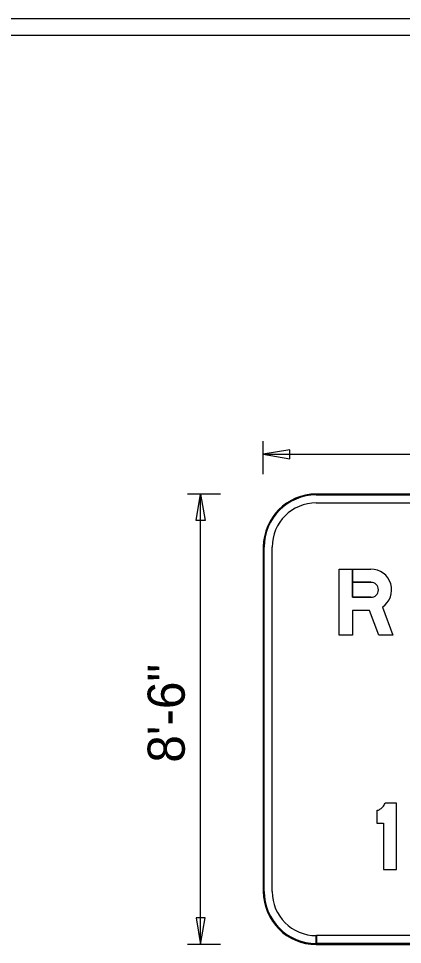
# Model space of a CAD drawing. Extents: x 10268147 to 10268469, y 2141099 to 2141204.
# Drawn here: x 10268191.41 to 10268198.66, y 2141186.48 to 2141203.96 of the extents above; entities that cross this region are included whole.
import ezdxf

# ---------------------------------------------------------------- set-up
doc = ezdxf.new("R2010")
doc.units = 0
for name, color, linetype in [('61', 7, 'Continuous'), ('GSDims', 7, 'Continuous'), ('PlotBorder_dp', 7, 'Continuous'), ('SheetLinesMisc2_dp', 7, 'Continuous')]:
    doc.layers.add(name, color=color, linetype=linetype)

msp = doc.modelspace()

# ---------------------------------------------------------------- linework, layer by layer
at = {"layer": '61'}
msp.add_line((10268153.875, 2141203.638), (10268229.209, 2141203.638), dxfattribs=at)
at = {"layer": 'GSDims'}
for p, q in [((10268196.031, 2141195.358), (10268196.031, 2141195.983)), ((10268196.031, 2141195.733), (10268211.031, 2141195.733)), ((10268195.224, 2141194.983), (10268194.599, 2141194.983)), ((10268194.849, 2141186.483), (10268194.849, 2141194.983)), ((10268195.224, 2141186.483), (10268194.599, 2141186.483))]:
    msp.add_line(p, q, dxfattribs=at)
for points in [[(10268196.031, 2141195.733), (10268196.531, 2141195.65), (10268196.531, 2141195.817)], [(10268194.849, 2141194.983), (10268194.932, 2141194.483), (10268194.766, 2141194.483)], [(10268194.849, 2141186.483), (10268194.932, 2141186.983), (10268194.766, 2141186.983)]]:
    msp.add_lwpolyline(points, close=True, dxfattribs=at)
at = {"layer": 'PlotBorder_dp'}
for p, q in [((10268210.031, 2141194.983), (10268197.031, 2141194.983)), ((10268210.031, 2141194.983), (10268197.031, 2141194.983)), ((10268210.031, 2141194.983), (10268197.031, 2141194.983)), ((10268210.031, 2141194.983), (10268197.031, 2141194.983)), ((10268197.031, 2141194.967), (10268210.031, 2141194.967)), ((10268197.031, 2141194.817), (10268210.031, 2141194.817)), ((10268197.031, 2141194.817), (10268210.031, 2141194.817)), ((10268196.031, 2141193.983), (10268196.031, 2141187.483)), ((10268196.031, 2141193.983), (10268196.031, 2141187.483)), ((10268196.031, 2141193.983), (10268196.031, 2141187.483)), ((10268196.031, 2141193.983), (10268196.031, 2141187.483)), ((10268196.047, 2141187.483), (10268196.047, 2141193.983)), ((10268196.197, 2141187.483), (10268196.197, 2141193.983)), ((10268196.197, 2141187.483), (10268196.197, 2141193.983)), ((10268197.031, 2141186.483), (10268197.031, 2141186.65)), ((10268197.031, 2141186.483), (10268197.031, 2141186.65)), ((10268210.031, 2141186.65), (10268197.032, 2141186.65)), ((10268197.032, 2141186.65), (10268197.032, 2141186.483)), ((10268210.031, 2141186.65), (10268197.032, 2141186.65)), ((10268197.032, 2141186.65), (10268197.032, 2141186.483)), ((10268197.031, 2141186.483), (10268197.031, 2141186.5)), ((10268210.031, 2141186.5), (10268197.031, 2141186.5)), ((10268197.031, 2141186.5), (10268197.031, 2141186.483)), ((10268197.031, 2141186.483), (10268210.031, 2141186.483)), ((10268197.031, 2141186.483), (10268210.031, 2141186.483)), ((10268197.032, 2141186.483), (10268210.031, 2141186.483)), ((10268197.032, 2141186.483), (10268210.031, 2141186.483))]:
    msp.add_line(p, q, dxfattribs=at)
for points in [[(10268198.278, 2141192.85), (10268198.477, 2141192.317), (10268198.21, 2141192.317), (10268198.036, 2141192.784), (10268197.714, 2141192.784), (10268197.714, 2141192.317), (10268197.464, 2141192.317), (10268197.464, 2141193.567), (10268197.714, 2141193.567), (10268197.714, 2141193.034)], [(10268198.278, 2141192.85), (10268198.477, 2141192.317), (10268198.21, 2141192.317), (10268198.036, 2141192.784), (10268197.714, 2141192.784), (10268197.714, 2141192.317), (10268197.464, 2141192.317), (10268197.464, 2141193.567), (10268197.714, 2141193.567), (10268197.714, 2141193.034)], [(10268198.278, 2141192.85), (10268198.477, 2141192.317), (10268198.21, 2141192.317), (10268198.036, 2141192.784), (10268197.714, 2141192.784), (10268197.714, 2141192.317), (10268197.464, 2141192.317), (10268197.464, 2141193.567), (10268198.061, 2141193.567)], [(10268198.061, 2141193.317), (10268197.714, 2141193.317), (10268197.714, 2141193.567), (10268198.061, 2141193.567)], [(10268198.061, 2141193.317), (10268197.714, 2141193.317), (10268197.714, 2141193.567), (10268198.061, 2141193.567)], [(10268198.061, 2141193.034), (10268197.714, 2141193.034), (10268197.714, 2141193.317), (10268198.061, 2141193.317)], [(10268197.714, 2141193.034), (10268198.061, 2141193.034)], [(10268197.714, 2141193.034), (10268198.061, 2141193.034)], [(10268198.172, 2141189.01), (10268198.172, 2141188.772), (10268198.301, 2141188.772), (10268198.301, 2141187.9), (10268198.547, 2141187.9), (10268198.547, 2141189.15), (10268198.331, 2141189.15)], [(10268198.172, 2141189.01), (10268198.172, 2141188.772), (10268198.301, 2141188.772), (10268198.301, 2141187.9), (10268198.547, 2141187.9), (10268198.547, 2141189.15), (10268198.331, 2141189.15)], [(10268198.172, 2141189.01), (10268198.172, 2141188.772), (10268198.301, 2141188.772), (10268198.301, 2141187.9), (10268198.547, 2141187.9), (10268198.547, 2141189.15), (10268198.331, 2141189.15)]]:
    msp.add_lwpolyline(points, dxfattribs=at)
for centre, radius, start, end in [((10268197.031, 2141193.983), 1, 90, 180), ((10268197.031, 2141193.983), 1, 90, 180), ((10268197.031, 2141193.983), 1, 90, 180), ((10268197.031, 2141193.983), 1, 90, 180), ((10268197.031, 2141193.983), 0.983, 90, 180), ((10268197.031, 2141193.983), 0.833, 90, 180), ((10268197.031, 2141193.983), 0.833, 90, 180), ((10268197.031, 2141187.483), 1, 180, 270), ((10268197.031, 2141187.483), 1, 180, 270), ((10268197.031, 2141187.483), 1, 180, 270), ((10268197.031, 2141187.483), 1, 180, 270), ((10268197.031, 2141187.483), 0.983, 180, 270), ((10268197.031, 2141187.483), 0.833, 180, 270), ((10268197.031, 2141187.483), 0.833, 180, 270)]:
    msp.add_arc(centre, radius, start, end, dxfattribs=at)
for centre, major_axis, ratio, start_param, end_param in [((10268198.061, 2141193.175), (0, 0.391), 0.999998, 3.731228, 6.283185), ((10268198.061, 2141193.175), (0, 0.391), 0.999998, 3.731228, 6.283185), ((10268198.061, 2141193.175), (0, 0.391), 0.999998, 3.731228, 6.283185), ((10268198.061, 2141193.175), (0, 0.141), 0.999998, 3.141593, 6.283185), ((10268198.061, 2141193.175), (0, 0.141), 0.999998, 3.141593, 6.283185), ((10268198.061, 2141193.175), (0, 0.141), 0.999998, 3.141593, 6.283185), ((10268198.121, 2141189.228), (0, 0.223), 0.999996, 3.372996, 3.659448), ((10268198.121, 2141189.228), (0, 0.223), 0.999996, 3.372996, 3.659448), ((10268198.121, 2141189.228), (0, 0.223), 0.999996, 3.372996, 3.659448), ((10268198.121, 2141189.228), (0, 0.223), 0.999996, 3.659448, 3.945901), ((10268198.121, 2141189.228), (0, 0.223), 0.999996, 3.659448, 3.945901), ((10268198.121, 2141189.228), (0, 0.223), 0.999996, 3.659448, 3.945901), ((10268198.121, 2141189.228), (0, 0.223), 0.999996, 3.945901, 4.150196), ((10268198.121, 2141189.228), (0, 0.223), 0.999996, 3.945901, 4.150196), ((10268198.121, 2141189.228), (0, 0.223), 0.999996, 3.945901, 4.150196), ((10268198.121, 2141189.228), (0, 0.223), 0.999996, 4.150196, 4.354491), ((10268198.121, 2141189.228), (0, 0.223), 0.999996, 4.150196, 4.354491), ((10268198.121, 2141189.228), (0, 0.223), 0.999996, 4.150196, 4.354491)]:
    msp.add_ellipse(centre, major_axis=major_axis, ratio=ratio, start_param=start_param, end_param=end_param, dxfattribs=at)
at = {"layer": 'SheetLinesMisc2_dp'}
msp.add_line((10268153.14, 2141203.955), (10268306.32, 2141203.955), dxfattribs=at)

# ---------------------------------------------------------------- texts
at = {"layer": 'GSDims'}
msp.add_text('8\'-6"', height=0.7, rotation=90, dxfattribs=at).set_placement((10268194.549, 2141189.913))

doc.saveas('drawing.dxf')
